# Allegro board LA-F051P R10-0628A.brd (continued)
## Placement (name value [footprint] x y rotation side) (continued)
PC1208  -  [C_0603]  130.4 65.17 270 top
PC1209  -  [C_0603]  129.13 65.17 270 top
PC1210  -  [C_0603]  99.52 58.77 270 bottom
PC1211  -  [C_0603]  99.77 66.09 270 top
PC1212  -  [C_0603]  97.04 61.85 90 bottom
PC1213  -  [C_0603]  92.46 42.86 270 bottom
PC1214  -  [C_0603]  98.35 61.85 90 top
PC1215  -  [C_0603]  97.04 61.85 90 top
PC1216  -  [C_0603]  95.86 71.71 90 top
PC1217  -  [C_0603]  110.39 64.61 90 top
PC1218  -  [C_0603]  99.64 61.83 90 bottom
PC1219  -  [C_0603]  126.14 58.81 90 top
PC1220  -  [C_0603]  123.67 58.12 90 top
PC1221  -  [C_0603]  126.09 65.24 270 top
PC1222  -  [C_0603]  124.82 65.24 270 top
PC1223  -  [C_0603]  123.55 65.24 270 top
PC1224  -  [C_0603]  109.12 64.55 90 top
PC1225  -  [C_0603]  126.09 61.17 90 top
PC1226  -  [C_0603]  111.66 64.61 90 top
PC1227  -  [C_0603]  115.29 64.6 90 top
PC1228  -  [C_0603]  123.55 61.17 90 top
PC1229  -  [C_0603]  112.88 64.6 90 top
PC1230  -  [C_0603]  98.3 71.71 90 top
PC1231  -  [C_0603]  94.15 42.87 270 bottom
PC1232  -  [C_0603]  101.07 69.49 270 bottom
PC1233  -  [C_0603]  97.08 71.71 90 top
PC1234  -  [C_0603]  102.27 69.49 270 bottom
PC1235  -  [C_0603]  100.98 66.09 270 top
PC1236  -  [C_0603]  98.57 66.09 270 top
PC1237  -  [C_0603]  129.9 75.78 180 bottom
PC1238  -  [C_0603]  98.4 71.73 90 bottom
PC1239  -  [C_0603]  97.13 71.73 90 bottom
PC1240  -  [C_0603]  98.34 61.83 90 bottom
PC1241  -  [C_0603]  95.86 71.73 90 bottom
PC1242  -  [C_0603]  102.27 69.49 270 top
PC1243  -  [C_0603]  103.47 69.49 270 top
PC1244  -  [C_0603]  92.46 42.86 270 top
PC1245  -  [C_0603]  101.07 69.49 270 top
PC1246  -  [C_0603]  103.47 69.49 270 bottom
PC1250  -  [C_0603]  102.18 66.09 270 top
PC1251  -  [C_0603]  103.39 66.09 270 top
PC1252  -  [C_0603]  104.59 66.09 270 top
PC1256  -  [C_0603]  101.07 61.81 90 top
PC1257  -  [C_0603]  99.68 61.86 90 top
PC1258  -  [C_0603]  107.54 61.81 90 top
PC1259  -  [C_0201]  134.58 66.02 0 top
PC1260  -  [C_0201]  127.74 63.46 180 top
PC1261  -  [C_0201]  127.74 60.92 180 top
PC1262  -  [C_0201]  134.47 60.28 0 top
PC1263  -  [C_0201]  134.47 65.36 0 top
PC1264  -  [C_0201]  134.47 61.55 0 top
PC1265  -  [C_0201]  134.47 62.82 0 top
PC1266  -  [C_0201]  127.74 59.65 180 top
PC1267  -  [C_0201]  127.74 62.82 180 top
PC1268  -  [C_0201]  127.74 64.73 180 top
PC1269  -  [C_0201]  127.15 66.73 90 top
PC1270  -  [C_0201]  99.59 68.06 0 top
PC1271  -  [C_0201]  99.59 67.5 0 top
PC1272  -  [C_0201]  126.57 66.76 90 top
PC1273  -  [C_0201]  99.58 68.63 0 top
PC1274  -  [C_0201]  125.4 66.76 90 top
PC1275  -  [C_0201]  128.75 67.78 0 top
PC1276  -  [C_0201]  116.28 67.75 180 top
PC1277  -  [C_0201]  116.19 65.45 90 top
PC1278  -  [C_0201]  120.37 56.85 270 top
PC1279  -  [C_0201]  120.98 56.78 0 top
PC1280  -  [C_0201]  123.8 56.85 270 top
PC1281  -  [C_0201]  126.21 56.85 270 top
PC1282  -  [C_0201]  119.1 56.85 270 top
PC1283  -  [C_0201]  125.07 56.85 270 top
PC1284  -  [C_0201]  116.59 67.18 180 top
PC1285  -  [C_0201]  127.36 56.77 270 top
PC1286  -  [C_0201]  118.85 64.42 270 top
PC1287  -  [C_0201]  118.25 64.42 270 top
PC1288  -  [C_0201]  127.74 61.55 180 top
PC1289  -  [C_0201]  125.98 66.79 90 top
PC1290  -  [C_0201]  99.59 66.93 0 top
PC1291  -  [C_0201]  132.28 56.73 0 top
PC1292  -  [C_0201]  131.69 56.17 180 top
PC1293  -  [C_0201]  127.74 59.01 180 top
PC1294  -  [C_0201]  134.47 60.92 0 top
PC1295  -  [C_0201]  134.47 62.19 0 top
PC1296  -  [C_0201]  134.47 64.73 0 top
PC1297  -  [C_0201]  127.74 60.28 180 top
PC1298  -  [C_0201]  127.74 62.19 180 top
PC1299  -  [C_0201]  127.74 64.09 180 top
PC1300  -  [C_0201]  127.46 67.98 180 top
PC1301  -  [C_0201]  133.71 55.58 90 top
PC1302  -  [C_0201]  134.47 63.46 0 top
PC1303  -  [C_0201]  131.67 56.73 180 top
PC1304  -  [C_0201]  134.47 64.09 0 top
PC1305  -  [C_0201]  132.27 56.17 0 top
PC1306  -  [C_B2]  97.21 45.98 90 bottom
PC1307  -  [C_B2]  98.03 51.19 0 bottom
PC1308  -  [C_B2]  97.18 59 90 bottom
PC1309  -  [C_B2]  97.16 65.6 180 bottom
PC1310  -  [C_0603]  133.15 73.34 90 top
PC1311  -  [C_0603]  137.71 72.83 270 top
PC1312  -  [C_0603]  76.68 67.01 180 bottom
PC1313  -  [C_0603]  134.38 73.36 90 top
PC1314  -  [C_0603]  135.67 73.36 90 top
PC1315  -  [C_0603]  136.97 68.79 90 top
PC1316  -  [C_0603]  138.79 64.86 0 top
PC1317  -  [C_0603]  138.02 59.9 0 top
PC1318  -  [C_0603]  137.64 63.71 180 top
PC1319  -  [C_0603]  137.64 66.25 180 top
PC1320  -  [C_0603]  137.64 64.98 180 top
PC1321  -  [C_0603]  76.68 68.28 180 bottom
PC1322  -  [C_0201]  138.28 58.63 180 top
PC1323  -  [C_0201]  138.88 58.63 0 top
PC1324  -  [C_0201]  138.66 67.9 0 top
PC1325  -  [C_0201]  137.64 67.9 180 top
PC1326  -  [C_0201]  136.41 67.78 180 top
PC1327  -  [C_0201]  135.69 68.73 90 top
PC1328  -  [C_0201]  134.85 66.63 0 top
PC1329  -  [C_B2]  96.79 68.79 180 bottom
PC1330  -  [C_0603]  124.82 61.17 90 top
PC1331  -  [C_0603]  102.46 61.81 90 top
PC1332  -  [C_0603]  103.73 61.81 90 top
PC1333  -  [C_0603]  119.86 58.12 90 top
PC1334  -  [C_0603]  108.81 61.81 90 top
PC1336  -  [C_0603]  124.89 58.81 90 top
PC1337  -  [C_0603]  122.4 58.12 90 top
PC1338  -  [C_0201]  119.25 67.52 90 top
PC1339  -  [C_0201]  121.12 67.51 90 top
PC1340  -  [C_0201]  120.19 67.5 90 top
PC1341  -  [C_0201]  118.42 67.88 180 top
PC1342  -  [C_0201]  117.2 66.72 90 top
PC1343  -  [C_0201]  116.76 65.46 90 top
PC1344  -  [C_0603]  121.13 58.12 90 top
PC1345  -  [C_0603]  111.35 61.81 90 top
PC1346  -  [C_0603]  110.08 61.81 90 top
PC1347  -  [C_0603]  122.28 65.11 270 top
PC1348  -  [C_0603]  121.01 65.11 270 top
PC1349  -  [C_0603]  119.74 65.11 270 top
PC1350  -  [C_0603]  111.6 60.36 270 top
PC1351  -  [C_0603]  115.04 60.54 270 top
PC1352  -  [C_0603]  113.26 60.41 270 top
PC1353  -  [C_0603]  115.29 61.81 90 top
PC1354  -  [C_0603]  113.26 61.81 90 top
PC1400  -  [C_0402]  174.73 53.48 90 top
PC1401  -  [C_0603]  177.78 51.52 0 bottom
PC1402  -  [C_0603]  177.78 50.91 0 top
PC1403  -  [C_0603]  169.58 52.16 0 top
PC1404  -  [C_0603]  167.87 50.89 180 top
PC1405  -  [C_0603]  168.63 52.16 180 top
PC1406  -  [C_0603]  193.97 72.09 180 top
PC1408  -  [C_0402]  177.65 49.64 0 top
PC1409  -  [C_0402]  177.65 50.38 0 bottom
PC1410  -  [C_0402]  168 48.22 90 top
PC1411  -  [C_0402]  174.85 46.69 270 top
PC1412  -  [C_0402]  202.68 74.47 180 bottom
PC1413  -  [C_0603]  202.96 76.73 0 top
PC1414  -  [C_0603]  202.32 78.14 0 top
PC1415  -  [C_0603]  193.97 73.36 180 top
PC1416  -  [C_0603]  193.97 74.63 180 top
PC1417  -  [C_0402]  202.97 74.81 0 top
PC1418  -  [C_0402]  202.96 75.69 0 top
PC1419  -  [C_0402]  196.44 70.82 180 top
PC1420  -  [C_0402]  202.45 72.68 90 bottom
PC1535  -  [C_0402]  63.14 63.47 0 bottom
PC1536  -  [C_0402]  59.13 32.88 270 top
PC1537  -  [C_D]  81.34 32.22 0 bottom
PC1538  -  [C_0402]  64.75 48.52 0 bottom
PD100  -  [TVNST52302AB0_SOT523-3]  67.29 14.82 180 top
PD101  -  [TVNST52302AB0_SOT523-3]  68.81 15.25 90 top
PD102  -  [AZ5125-01HPR7G_SOD523-2]  26.96 72.27 90 top
PD200  -  [BAT54CW_SOT323-3]  59.67 56.46 90 top
PD201  -  [SDMK0340L-7-F_SOD323-2]  90.33 77.05 180 top
PD202  -  [SDMK0340L-7-F_SOD323-2]  52.35 50.64 0 top
PD203  -  [SDMK0340L-7-F_SOD323-2]  89.69 70.32 180 top
PD204  -  [SDMK0340L-7-F_SOD323-2]  59.12 68.16 180 top
PD205  -  [SDMK0340L-7-F_SOD323-2]  59.14 69.88 180 top
PD206  -  [SDMK0340L-7-F_SOD323-2]  96.97 74.7 0 top
PD300  -  [SDMK0340L-7-F_SOD323-2]  42.14 22.56 270 top
PD301  -  [SDMK0340L-7-F_SOD323-2]  37.69 19.77 270 top
PD302  -  [SDMK0340L-7-F_SOD323-2]  39.47 19.77 270 top
PH1005  -  [R_0402]  85.17 58.99 0 bottom
PH1006  -  [R_0402]  71.5 59.18 0 bottom
PH1007  -  [R_0402]  84.25 59.91 0 bottom
PH1008  -  [R_0402]  84.32 50.69 0 bottom
PH1009  -  [R_0402]  89.18 42.91 0 bottom
PJP14  -  [JUMP_43X39]  28.68 19.77 270 bottom
PJP15  -  [JUMP_43X39]  170.36 63.13 180 top
PJP300  -  [JUMP_43X39]  41.76 30.74 90 top
PJP500  -  [JUMP_43X118]  76.18 17.91 270 bottom
PJP501  -  [JUMP_43X118]  59.03 46.78 90 bottom
PJP600  -  [JUMP_43X118]  162.83 21.04 180 top
PJP601  -  [JUMP_43X39]  164.64 27.77 180 top
PJP700  -  [JUMP_43X79]  192.55 56.09 180 bottom
PJP800  -  [JUMP_43X39]  168.12 71.54 270 top
PJP900  -  [JUMP_43X39]  161.85 42 180 top
PJP1002  -  [JUMP_43X118]  73.68 41.87 180 bottom
PJP1400  -  [JUMP_43X79]  169.27 53.89 90 top
PJP1401  -  [JUMP_43X79]  193.4 69.55 180 top
PL100  -  [TAI-T_HCB2012KF-121T50_2P]  76.09 24.29 180 bottom
PL101  -  [TAI-T_HCB2012KF-121T50_2P]  76.09 26.09 180 bottom
PL102  -  [MURAT_BLM15AG102SN1D_2P]  26.22 71.03 0 top
PL103  -  [TAI-T_HCB2012KF-121T50_2P]  28.55 78.19 0 bottom
PL104  -  [TAI-T_HCB2012KF-121T50_2P]  25.38 73.11 90 top
PL300  -  [TAI-T_HCB2012KF-121T50_2P]  49.2 31.57 90 bottom
PL301  -  [L_7X7X3_M_2P]  59.58 32.6 0 bottom
PL500  -  [TAI-T_HCB2012KF-121T50_2P]  92.86 25.95 270 bottom
PL501  -  [TAI-T_TMPC0518HP-1R5MG-D_2P]  85.57 20.66 180 bottom
PL504  -  [CYNTE_PCMC063T-1R5MN_2P]  59.28 42 180 bottom
PL600  -  [TAI-T_HCB2012KF-121T50_2P]  172.23 36.46 180 top
PL601  -  [CYNTE_PCMB051B-1R0MS_2P]  169.52 26.63 270 top
PL700  -  [TAI-T_HCB2012KF-121T50_2P]  196.71 66.91 270 bottom
PL701  -  [L_5X5X3_M_2P]  198.53 59.54 270 bottom
PL800  -  [TAI-T_HCB1608KF-121T3_L0603_2P]  177.65 79.21 180 top
PL801  -  [TOKO_1239AS-H-2R2N-P2_2P]  170.03 75.52 180 top
PL900  -  [TAI-T_HCB1608KF-121T3_L0603_2P]  173.27 38.78 90 top
PL901  -  [TOKO_1239AS-H-2R2N-P2_2P]  165.33 44.03 180 top
PL1004  -  [TAI-T_HCB2012KF-121T50_2P]  64.75 61.78 180 bottom
PL1005  -  [MAG_MMD05CZR47M_4P]  72.49 62.4 0 bottom
PL1100  -  [L_7X7X3_M]  87.58 47.11 0 bottom
PL1101  -  [L_7X7X3_M]  87.63 55.25 0 bottom
PL1102  -  [L_7X7X3_M]  87.66 62.9 0 bottom
PL1400  -  [TAI-T_HCB1608KF-121T3_L0603_2P]  179.55 52.18 180 top
PL1401  -  [TOKO_1277AS-H-1R0N-P2_2P]  169.9 48.47 90 top
PL1402  -  [TAI-T_HCB1608KF-121T3_L0603_2P]  199.44 77.83 0 top
PL1403  -  [TOKO_1277AS-H-1R0N-P2_2P]  196.06 73.24 90 top
PQ100  -  [FDV301N_NL_SOT23-3]  27.65 69.25 180 top
PQ101  -  [MMST3904-7-F_SOT323-3]  31.68 72.06 0 top
PQ200  -  [AON2405_DFN6-8]  56 51.55 180 bottom
PQ201  -  [AON2405_DFN6-8]  56.21 56.36 270 bottom
PQ202  -  [AON2405_DFN6-8]  33.14 75.17 180 bottom
PQ203  -  [AON2405_DFN6-8]  34.42 75.25 90 bottom
PQ204  -  [NTR4502PT1G_SOT23-3]  57.86 50.86 0 top
PQ205  -  [NTR4502PT1G_SOT23-3]  18.77 76.82 180 top
PQ206  -  [DMN66D0LDW-7_SOT363-6]  58.4 55.7 90 top
PQ207  -  [DMN66D0LDW-7_SOT363-6]  34.87 75.61 180 top
PQ208  -  [DMN66D0LDW-7_SOT363-6]  62.96 47.57 90 top
PQ209  -  [DMN66D0LDW-7_SOT363-6]  21.07 72.92 180 top
PQ210  -  [AON2405_DFN6-8]  46.61 74.49 90 bottom
PQ211  -  [AON2405_DFN6-8]  46.82 78.67 0 bottom
PQ212  -  [AON2405_DFN6-8]  45.57 76.92 180 bottom
PQ213  -  [NTR4502PT1G_SOT23-3]  57.96 61.77 180 top
PQ214  -  [NTR4502PT1G_SOT23-3]  47.85 73.16 90 top
PQ215  -  [DMN66D0LDW-7_SOT363-6]  60.08 65.48 180 top
PQ216  -  [DMN66D0LDW-7_SOT363-6]  57.7 65.48 180 top
PQ217  -  [DMN66D0LDW-7_SOT363-6]  55.08 73.1 90 top
PQ218  -  [DMN66D0LDW-7_SOT363-6]  88.43 68.55 270 top
PQ219  -  [DMN66D0LDW-7_SOT363-6]  62.44 19.84 0 top
PQ220  -  [SSM3K7002FU_SC70-3]  58.72 20.53 270 top
PQ221  -  [NTR4502PT1G_SOT23-3]  56.24 40.47 180 top
PQ222  -  [NTR4502PT1G_SOT23-3]  64.48 33.96 90 top
PQ223  -  [DMN66D0LDW-7_SOT363-6]  58.18 32.86 90 top
PQ224  -  [SSM3K7002FU_SC70-3]  56.06 67.5 0 bottom
PQ302  -  [L2N7002WT1G_SC70-3]  39.02 22.58 90 top
PQ303  -  [SIR472DP-T1-GE3_POWERPAK8-5]  56.64 29.54 270 bottom
PQ304  -  [SI7716ADN-T1-GE3_POWERPAK8-5]  54.09 31.62 90 bottom
PQ305  -  [SI4483ADY-T1-GE3_SO8]  74.24 33.33 0 bottom
PQ400  -  [DMN66D0LDW-7_SOT363-6]  166.79 58.27 270 top
PQ1302  -  [AON7934_DFN3X3A8-10]  69.85 62.15 180 bottom
PR100  -  [R_0402]  66.02 18.88 270 top
PR101  -  [R_0402]  27.97 71.05 0 top
PR102  -  [R_0402]  23.44 69.8 270 top
PR103  -  [R_0402]  25.24 68.75 180 top
PR104  -  [R_0402]  28.93 72.02 90 top
PR105  -  [R_0402]  33.39 72.62 0 top
PR106  -  [R_0402]  29.82 72.93 270 top
PR107  -  [R_0805]  29.21 76.51 270 top
PR108  -  [R0402_0OHM]  28 72.01 90 top
PR200  -  [R_1206_4P-D]  55.07 58.87 90 bottom
PR201  -  [R_0402]  60.27 51.61 90 top
PR202  -  [R_0402]  55.14 54.06 0 bottom
PR203  -  [R_0402]  29.44 76.74 270 bottom
PR204  -  [R_0402]  18.59 72.98 180 top
PR205  -  [R_0402]  35.74 78.95 180 bottom
PR206  -  [R_0402]  21.23 76.29 0 top
PR207  -  [R_0402]  59.35 54.73 0 top
PR208  -  [R_0402]  34.49 76.55 180 top
PR209  -  [R_0402]  31.48 75.1 0 top
PR210  -  [R_0402]  60.94 45.69 90 top
PR211  -  [R_0402]  17.68 72.09 0 top
PR212  -  [R_0402]  20.22 70.06 0 top
PR213  -  [R_0402]  61.68 58.51 0 top
PR214  -  [R_0402]  61.02 62.59 270 bottom
PR215  -  [R_0402]  22.15 77.3 180 top
PR216  -  [R_0402]  60.52 59.13 270 top
PR217  -  [R_0402]  21.18 74.96 270 top
PR218  -  [R_0402]  62.09 49.93 180 top
PR219  -  [R_0402]  32.6 76.12 180 top
PR220  -  [R_0402]  22.07 74.96 270 top
PR221  -  [R_0402]  57.51 61.63 270 bottom
PR222  -  [R_0402]  56.62 59.78 90 bottom
PR223  -  [R_0402]  56.6 57.87 0 bottom
PR224  -  [R_0402]  92.25 73.62 180 top
PR225  -  [R_0402]  57.51 58.76 90 bottom
PR226  -  [R_0402]  87.4 75.52 0 top
PR227  -  [R_0402]  91.34 75.52 0 top
PR228  -  [R_0402]  36 74.35 270 top
PR229  -  [R_0402]  59.96 46.62 270 top
PR230  -  [R_0402]  91.34 72.73 0 top
PR232  -  [R_0402]  50.67 75.14 270 bottom
PR233  -  [R_0402]  59.49 66.26 90 bottom
PR234  -  [R_0402]  50.39 77.73 90 bottom
PR235  -  [R_0402]  49.53 71.79 0 top
PR237  -  [R_0402]  44.17 78.05 270 top
PR239  -  [R_0402]  51.36 79.59 180 bottom
PR240  -  [R_0402]  63.14 64.35 0 bottom
PR241  -  [R_0402]  51.56 75.28 90 bottom
PR242  -  [R_0402]  58.6 67.19 180 bottom
PR243  -  [R_0402]  50.44 80.48 0 bottom
PR244  -  [R_0402]  42.52 77.36 90 top
PR245  -  [R_0402]  49.56 72.67 0 top
PR246  -  [R_0402]  61.44 65.06 270 bottom
PR247  -  [R_0402]  54.42 64.3 90 bottom
PR248  -  [R_0402]  53.24 66.15 90 top
PR249  -  [R_0402]  52.9 68.64 180 top
PR250  -  [R_0402]  53.68 71.66 0 top
PR251  -  [R_0402]  51.35 72.22 0 top
PR252  -  [R_0402]  85.7 68.74 270 top
PR253  -  [R_0402]  92.25 68.8 180 top
PR254  -  [R_0402]  84 70.82 180 top
PR255  -  [R_0402]  63.22 23.66 270 top
PR256  -  [R_0402]  64.87 20.86 270 top
PR257  -  [R_0402]  62.33 23.66 270 top
PR258  -  [R_0402]  85.83 69.86 90 top
PR259  -  [R_0402]  64.95 16.47 180 top
PR260  -  [R_0402]  56.03 18.63 0 top
PR261  -  [R_0402]  56.03 20.41 0 top
PR262  -  [R_0402]  64.03 15.58 0 top
PR263  -  [R_0402]  58.4 15.27 270 top
PR264  -  [R_0402]  82.65 74.08 270 top
PR265  -  [R_0402]  86.59 68.74 270 top
PR266  -  [R_0402]  64.95 13.8 180 top
PR267  -  [R_0402]  59.28 14.36 90 top
PR268  -  [R_0402]  83.54 73.16 90 top
PR269  -  [R_0402]  84.38 72.22 180 top
PR270  -  [R_0402]  64.03 14.69 0 top
PR271  -  [R_0402]  64.03 17.36 0 top
PR272  -  [R_0402]  57.51 15.27 270 top
PR273  -  [R_0402]  56.95 17.48 180 top
PR274  -  [R_0402]  91.34 67.9 0 top
PR275  -  [R_0402]  56.02 36.67 0 top
PR277  -  [R_0402]  60.03 31.97 90 top
PR278  -  [R_0402]  60.55 34.63 270 top
PR279  -  [R_0402]  59.67 34.65 270 top
PR280  -  [R_0402]  57.38 54.66 0 top
PR281  -  [R_0402]  55.11 35.78 0 top
PR282  -  [R_0402]  60.11 47.57 90 top
PR283  -  [R_0402]  62.36 47.08 270 bottom
PR284  -  [R_0402]  60.36 62.56 180 top
PR285  -  [R_0402]  54.42 67 270 bottom
PR286  -  [R_0402]  58.06 66.8 180 top
PR287  -  [R_0402]  93.18 70.6 180 top
PR288  -  [R_0402]  91.39 69.69 90 top
PR289  -  [R_0402]  64.36 59 180 top
PR290  -  [R_0402]  59.27 57.98 180 top
PR291  -  [R_0402]  55.18 67.85 180 bottom
PR300  -  [R_1206_4P-D]  49.25 29.46 270 bottom
PR301  -  [R_0402]  35.92 23.02 270 top
PR303  -  [R0402_0OHM]  45.39 23.96 180 bottom
PR304  -  [R0402_0OHM]  45.39 24.85 180 bottom
PR305  -  [R_0402]  42.29 24.27 90 bottom
PR306  -  [R_1206]  44.04 22.95 90 top
PR307  -  [R_0402]  39.47 22.11 90 bottom
PR308  -  [R_0603]  45.95 29.8 0 bottom
PR309  -  [R0402_0OHM]  37.64 30.31 180 bottom
PR310  -  [R_0402]  38.58 22.11 90 bottom
PR311  -  [R0402_0OHM]  37.64 31.71 180 bottom
PR312  -  [R_0402]  41.25 24.27 90 bottom
PR313  -  [R_1206_4P-D]  72.15 33.23 180 bottom
PR314  -  [R0402_0OHM]  42.14 22.11 90 bottom
PR315  -  [R0402_0OHM]  38.46 24.27 90 bottom
PR316  -  [R_0402]  36.73 29.17 0 bottom
PR317  -  [R_0402]  41.25 23.02 270 bottom
PR318  -  [R0402_0OHM]  40.36 24.27 90 top
PR319  -  [R0402_0OHM]  40.48 26.82 180 top
PR320  -  [R_0402]  45.24 32.34 0 bottom
PR321  -  [R_1206]  56.9 35.52 180 bottom
PR322  -  [R_0402]  39.25 27.71 0 top
PR323  -  [R_0402]  41.61 33.64 90 bottom
PR324  -  [R_0603]  39.22 33.11 90 bottom
PR325  -  [R_0402]  37.69 32.98 0 top
PR326  -  [R0402_0OHM]  37.69 32.09 0 top
PR327  -  [R_0402]  38.58 33.87 180 top
PR400  -  [R_0402]  164.69 63.38 90 bottom
PR401  -  [R_0402]  167.44 57.24 180 bottom
PR402  -  [R_0402]  167.95 64.47 180 top
PR403  -  [R_0402]  169.01 60.23 270 top
PR404  -  [R_0402]  169.9 60.23 270 top
PR405  -  [R_0402]  166.52 58.12 0 bottom
PR406  -  [R_0402]  167.03 63.59 0 top
PR407  -  [R_0402]  174.14 55.71 0 top
PR408  -  [R_0402]  167.95 62.7 180 top
PR409  -  [R_0402]  167.95 61.81 180 top
PR410  -  [R_0402]  166.6 59.06 90 bottom
PR411  -  [R_0402]  163.81 60.79 270 bottom
PR412  -  [R_0402]  167.03 60.92 0 top
PR413  -  [R_0402]  165.71 59.98 270 bottom
PR500  -  [R_0603]  88.81 22.31 180 top
PR501  -  [R_1206]  84.68 21.1 90 top
PR502  -  [R_0402]  88.37 17.94 270 bottom
PR503  -  [R0402_0OHM]  91.03 17.03 90 bottom
PR504  -  [R_0402]  89.26 17.03 90 bottom
PR505  -  [R_0603]  62.41 43.79 180 top
PR506  -  [R_0402]  67.16 38.36 90 bottom
PR507  -  [R_1206]  59.25 42.25 270 top
PR508  -  [R_0402]  66.27 38.36 90 bottom
PR509  -  [R_0402]  65.38 39.28 270 bottom
PR510  -  [R0402_0OHM]  64.49 38.36 90 bottom
PR511  -  [R_0402]  62.71 38.36 90 bottom
PR512  -  [R0805_0OHM]  70.28 42.67 90 top
PR513  -  [R0805_0OHM]  70.28 42.67 90 bottom
PR600  -  [R_0402]  175.29 35.26 0 top
PR601  -  [R_0402]  175.29 34.38 0 top
PR602  -  [R_0603]  172.96 25.59 270 top
PR603  -  [R_0402]  173.41 31.58 180 top
PR604  -  [R_0402]  173.41 34.25 180 top
PR605  -  [R_0402]  172.49 32.47 0 top
PR606  -  [R0402_0OHM]  172.49 33.36 0 top
PR607  -  [R0402_0OHM]  166.73 33.87 270 top
PR608  -  [R_0402]  165.84 32.98 90 top
PR609  -  [R0402_0OHM]  163.04 31.2 0 top
PR610  -  [R_0402]  163.93 30.31 180 top
PR611  -  [R_0402]  163.04 32.09 0 top
PR612  -  [R_0603]  172.54 27.87 0 top
PR700  -  [R_0402]  204.05 67.17 180 bottom
PR701  -  [R_0402]  203.15 66.29 0 bottom
PR702  -  [R_0603]  202.03 60.92 270 bottom
PR703  -  [R_0603]  198.98 62.63 270 top
PR704  -  [R_0402]  203.98 62.73 180 bottom
PR705  -  [R_0402]  200.67 66.71 90 bottom
PR707  -  [R_0402]  203.14 64.51 0 bottom
PR708  -  [R_0402]  203.14 63.13 90 top
PR709  -  [R0402_0OHM]  204.03 64.04 270 top
PR800  -  [R_0402]  173.08 78.95 270 top
PR801  -  [R0402_0OHM]  172.2 78.95 270 top
PR802  -  [R_0402]  171.55 70.82 90 top
PR803  -  [R_0603]  170.03 77.43 90 top
PR804  -  [R_0402]  172.44 71.71 270 top
PR805  -  [R_0402]  169.77 70.8 90 top
PR806  -  [R0402_0OHM]  173.33 70.8 90 top
PR900  -  [R0402_0OHM]  173.2 43.4 180 top
PR901  -  [R_0402]  173.2 44.28 180 top
PR902  -  [R_0402]  167.62 38.19 90 top
PR903  -  [R_0805]  165.29 41.87 180 top
PR904  -  [R_0402]  165.79 38.95 180 top
PR905  -  [R_0402]  165.41 40.47 180 top
PR906  -  [R0402_0OHM]  169.01 38.11 90 top
PR1024  -  [R0402_0OHM]  61.44 53.81 0 top
PR1025  -  [R0402_0OHM]  61.44 54.7 0 top
PR1027  -  [R0402_0OHM]  63.6 51.01 0 top
PR1028  -  [R_0402]  63.6 54.7 0 top
PR1029  -  [R0402_0OHM]  63.6 50.12 0 top
PR1058  -  [R_0402]  65.76 58.17 90 bottom
PR1059  -  [R0402_0OHM]  63.3 65.24 180 top
PR1060  -  [R_0402]  71.48 58.25 90 top
PR1061  -  [R_0402]  71.48 48.22 90 bottom
PR1062  -  [R_0402]  70.59 46.82 0 bottom
PR1063  -  [R_0402]  64.49 53.81 180 bottom
PR1064  -  [R_0402]  74.78 52.28 180 top
PR1065  -  [R_0402]  67.79 46.06 90 top
PR1066  -  [R0402_0OHM]  63.48 55.58 90 bottom
PR1067  -  [R_0402]  65 46.06 90 top
PR1068  -  [R_0402]  74.91 57.62 0 top
PR1069  -  [R_0402]  70.49 56.63 270 bottom
PR1070  -  [R_0402]  63.6 52.92 0 top
PR1071  -  [R_0402]  71.1 51.39 0 bottom
PR1072  -  [R_0402]  65.13 48.09 90 top
PR1073  -  [R_0402]  70.59 58.25 90 top
PR1074  -  [R_0402]  64.49 54.7 180 bottom
PR1075  -  [R_0402]  66.65 58.17 90 top
PR1076  -  [R0402_0OHM]  63.6 53.81 0 top
PR1077  -  [R_0402]  69.57 58.25 180 top
PR1078  -  [R_0402]  73.64 55.13 0 bottom
PR1079  -  [R_0402]  73.89 54.06 270 top
PR1080  -  [R0402_0OHM]  65.8 55.23 90 bottom
PR1081  -  [R_0402]  75.79 53.17 180 top
PR1082  -  [R_0603]  61.57 62.82 90 top
PR1083  -  [R0402_0OHM]  64.24 48.09 90 top
PR1084  -  [R_0402]  64.49 52.92 180 bottom
PR1085  -  [R_0402]  74.91 56.73 0 top
PR1086  -  [R_1206]  73.25 67.4 180 bottom
PR1087  -  [R_0402]  72.37 48.22 90 bottom
PR1088  -  [R_0402]  69.57 46.95 270 bottom
PR1089  -  [R_0402]  64.87 58.17 90 bottom
PR1090  -  [R_0402]  67.56 56.66 180 bottom
PR1091  -  [R_0603]  65.7 60.16 180 bottom
PR1092  -  [R_0402]  67.54 60.03 180 top
PR1093  -  [R_0402]  68.68 48.22 180 top
PR1094  -  [R_0402]  64.49 55.58 180 top
PR1095  -  [R_0402]  63.6 51.9 0 top
PR1096  -  [R_0402]  76.18 52.28 0 top
PR1097  -  [R_0402]  73.76 54.24 0 bottom
PR1098  -  [R_0402]  68.81 45.93 90 top
PR1099  -  [R_0402]  66.69 51.52 270 bottom
PR1100  -  [R_0603]  77.33 49.98 0 bottom
PR1101  -  [R_1206]  87.9 47.67 180 top
PR1102  -  [R_0603]  75.03 57.97 180 bottom
PR1103  -  [R0402_0OHM]  78.75 47.1 180 bottom
PR1105  -  [R_0603]  78.16 56.71 90 bottom
PR1106  -  [R_1206]  87.78 55.29 180 top
PR1107  -  [R_0402]  76.24 48.1 270 bottom
PR1109  -  [R_0402]  74.59 49.03 90 bottom
PR1110  -  [R0402_0OHM]  78.36 54.81 180 bottom
PR1111  -  [R_0603]  75.67 50.5 270 bottom
PR1112  -  [R_0402]  73.7 49.03 90 bottom
PR1113  -  [R_0603]  79.57 67.6 270 bottom
PR1114  -  [R_1206]  87.77 63.65 180 top
PR1115  -  [R_0402]  74.52 46.9 270 bottom
PR1116  -  [R_0603]  73.44 47.96 0 bottom
PR1118  -  [R_0402]  73.64 46.9 270 bottom
PR1119  -  [R0402_0OHM]  77.38 57.68 270 top
PR1120  -  [R_0402]  73.62 45.11 0 bottom
PR1121  -  [R_0402]  64.49 56.6 180 top
PR1122  -  [R_0402]  66.02 48.09 90 top
PR1123  -  [R_0402]  71.13 54.05 0 bottom
PR1124  -  [R_0402]  61.44 51.9 0 top
PR1125  -  [R0402_0OHM]  61.44 52.92 0 top
PR1126  -  [R_0402]  73.81 51.39 0 top
PR1127  -  [R_0402]  69.7 49.11 270 top
PR1128  -  [R_0402]  73.76 50.5 0 top
PR1400  -  [R0402_0OHM]  172.95 54.39 270 top
PR1401  -  [R0402_0OHM]  176.51 54.26 270 top
PR1402  -  [R_0402]  175.62 53.35 90 top
PR1403  -  [R_0603]  170.35 47.2 180 top
PR1404  -  [R_0402]  176.63 45.81 90 top
PR1405  -  [R_0402]  178.21 47.76 90 top
PR1406  -  [R_0402]  175.74 46.69 270 top
PR1407  -  [R_0402]  177.32 48.68 270 top
PR1408  -  [R_0402]  171.3 45.81 90 top
PR1409  -  [R0402_0OHM]  172.19 46.69 270 top
PR1411  -  [R0402_0OHM]  196.34 79.87 270 top
PR1412  -  [R_0402]  203.59 73.43 90 bottom
PR1413  -  [R_0402]  202.68 75.36 180 bottom
PR1414  -  [R_0402]  204.06 69.43 90 top
PR1415  -  [R_0402]  203.89 72.98 180 top
PR1416  -  [R_0603]  195.17 71.97 0 top
PR1417  -  [R_0402]  202.92 71.21 0 top
PR1418  -  [R_0402]  202.97 73.87 0 top
PR1419  -  [R0402_0OHM]  203.89 72.09 180 top
PR1420  -  [R0402_0OHM]  203.18 69.43 90 top
PR1421  -  [R0402_0OHM]  200.67 72.68 90 bottom
PR1422  -  [R_0402]  201.56 72.68 90 bottom
PR1423  -  [R_0402]  173.84 54.39 270 top
PR1424  -  [R_0402]  197.23 79.87 270 top
PR1425  -  [R_0402]  63.88 48.24 90 bottom
PRP100  -  [RP_0804_8P4R]  67.16 17.87 90 top
PU200  -  [INA199A1DCKR_SC70-6]  59.81 59.01 180 bottom
PU201  -  [LM393DMR2G_MICRO8]  89.85 72.01 90 top
PU202  -  [RT9069-33GB_SOT23-5]  65.41 67.45 270 bottom
PU203  -  [LM393DMR2G_MICRO8]  58.18 18.46 270 top
PU300  -  [BQ24777ARUYR_WQFN28_4X4]  42.9 27.26 90 bottom
PU400  -  [LM393DMR2G_MICRO8]  163.85 59.94 0 top
PU401  -  [M74VHC1GT00DFT2G_SC70-5]  169.71 58.27 270 top
PU402  -  [M74VHC1GT00DFT2G_SC70-5]  172.51 58.27 270 top
PU500  -  [SY8286BRAC_QFN20_3X3]  88.88 22.31 270 bottom
PU501  -  [SY8288CRAC_QFN20_3X3]  62.59 44.03 270 bottom
PU600  -  [SY8210AQVC_QFN19_4X3]  168 32.67 0 top
PU700  -  [SY8286RAC_QFN20_3X3]  198.48 62.91 0 bottom
PU800  -  [TLV62150RGTR_QFN16_3X3]  171.68 75.78 270 top
PU900  -  [TLV62150RGTR_QFN16_3X3]  166.98 42.88 270 top
PU1000  -  [ISL95859AHRTZ-T_TQFN40_5X5]  67.16 51.01 90 top
PU1100  -  [AOZ5049QI_QFN24_5X3P5-S]  80 46.71 90 bottom
PU1101  -  [AOZ5049QI_QFN24_5X3P5-S]  80.06 54.63 90 bottom
PU1102  -  [AOZ5049QI_QFN24_5X3P5-S]  80.06 62.21 90 bottom
PU1305  -  [ISL95808HRZ-TS2378_DFN8_2X2]  62.97 61.68 0 top
PU1400  -  [TPS62134ARGT_QFN16_3X3]  172.92 50.62 0 top
PU1401  -  [TPS62134BRGT_QFN16_3X3]  198.48 75.35 0 top
Q40  -  [L2N7002WT1G_SC-70-3]  183.57 18.62 180 top
Q41  -  [L2N7002WT1G_SC-70-3]  7.28 5.95 90 top
Q70  -  [SI3457BDV-T1-E3_TSOP6]  198.41 18.99 270 top
Q71  -  [L2N7002WT1G_SC-70-3]  203.37 17.74 90 top
Q72  -  [DMG2301U-7_SOT23-3]  198.16 46.06 90 top
QA1  -  [DMN66D0LDW-7_SOT363-6]  16.72 25.68 0 top
QA3  -  [DMN66D0LDW-7_SOT363-6]  16.37 32.09 180 top
QA6  -  [SSM3K7002FU_SC70-3]  19.03 31.52 180 top
QA9  -  [SSM3K7002FU_SC70-3]  19.28 24.53 180 top
QC2  -  [DMN66D0LDW-7_SOT363-6]  158.22 63.33 0 top
QE3  -  [MMBT3904WT1G_SC70-3]  135.99 61.81 270 top
QE4  -  [MMBT3904WT1G_SC70-3]  109.58 45.55 270 bottom
QE8  -  [MMBT3904WT1G_SC70-3]  193.9 79.97 180 top
QE9  -  [MMST3904-7-F_SOT323-3]  175.11 68.99 0 top
QE10  -  [MMBT3904WT1G_SC70-3]  148.95 36.66 0 top
QE11  -  [MMBT3904WT1G_SC70-3]  26.33 56.92 270 bottom
QE12  -  [DMN66D0LDW-7_SOT363-6]  187.55 74.76 270 top
QE13  -  [DMN66D0LDW-7_SOT363-6]  158.58 37.24 0 top
QE14  -  [DMN66D0LDW-7_SOT363-6]  34.18 35.23 270 top
QH7  -  [DMN66D0LDW-7_SOT363-6]  189.71 15.07 0 top
QH8  -  [DMN66D0LDW-7_SOT363-6]  9.05 7.75 90 top
QH9  -  [DMN66D0LDW-7_SOT363-6]  9.05 10.17 90 top
QT19  -  [L2N7002WT1G_SC-70-3]  27.74 54.14 180 bottom
QZ9  -  [DMG2301U-7_SOT23-3]  57.12 73.09 270 top
R7  -  [R_0402]  27.18 37.17 90 top
R9  -  [R_0201]  141.07 57.43 270 top
R10  -  [R_0201]  158.66 60.55 270 top
R60  -  [R_0201]  186.42 49.12 90 top
R78  -  [R_0402]  159.04 40.99 270 top
R79  -  [R_0402]  160.71 36.09 180 top
R80  -  [R_0402]  32.79 34.83 270 top
R81  -  [R_0402]  37.06 35.12 90 top
R104  -  [R0402_0OHM]  42.63 53.3 90 bottom
R220  -  [R_0402]  185.65 40.6 270 bottom
R249  -  [R_0402]  188.98 63.41 270 bottom
R250  -  [R0402_0OHM]  188.09 63.23 180 bottom
R251  -  [R0402_0OHM]  191.44 62.95 180 top
R252  -  [R_0402]  173.2 67.52 0 top
R287  -  [R_0402]  188.49 28.79 0 bottom
R288  -  [R_0402]  188.49 27.9 0 bottom
R289  -  [R0402_0OHM]  203.1 31.96 270 top
R290  -  [R_0402]  54.66 19.26 180 top
R291  -  [R_0402]  198.78 27.9 0 top
R292  -  [R_0402]  198.78 26.5 0 top
R531  -  [R_0603]  196.06 17.8 90 top
R535  -  [R_0402]  199.67 14.31 0 top
R536  -  [R_0402]  201.52 15.27 270 top
R540  -  [R_0402]  193.02 27.52 180 top
R545  -  [R_0402]  193.02 29.42 180 top
R884  -  [R_0402]  162.79 15.2 0 top
R886  -  [R_0402]  163.68 17.23 180 top
R910  -  [R_0402]  6.2 5.93 180 top
R911  -  [R_0402]  6.2 9.48 180 top
R912  -  [R_0402]  6.2 8.59 180 top
R913  -  [R_0402]  6.2 7.71 180 top
R916  -  [R_0402]  6.2 6.82 180 top
R1006  -  [R_0402]  183.74 50.2 270 top
R1027  -  [R_0402]  204.14 42.38 180 top
R1103  -  [R_0402]  165.25 16.21 0 top
R1104  -  [R_0402]  189.71 18.25 0 top
R1105  -  [R_0402]  190.98 14.06 180 top
R1125  -  [R0603_0OHM]  30.71 40.79 270 top
R1140  -  [R_0402]  53.75 20.15 0 top
R1141  -  [R_0402]  53.75 21.04 0 top
R1161  -  [R_0402]  206.48 18.55 90 top
R1162  -  [R_0402]  61.06 76.46 90 top
R1175  -  [R_0402]  168.61 14.18 0 top
R1176  -  [R_0402]  172.31 14.97 270 top
R1178  -  [R_0402]  171.43 14.97 270 top
R1179  -  [R_0402]  62.12 75.76 90 top
R1186  -  [R_0402]  36.81 39 90 top
R1187  -  [R_0402]  181.08 36.04 270 top
R1188  -  [R_0402]  179.17 37.82 270 top
R1191  -  [R_0402]  158.73 51.14 180 top
R1200  -  [R0402_0OHM]  43.46 46.95 0 top
R1210  -  [R0402_0OHM]  43.36 47.81 0 top
R1212  -  [R0402_0OHM]  42.14 45.93 90 top
R1216  -  [R_0402]  23.67 52.79 180 top
R1255  -  [R_0402]  44.16 45.09 270 top
R1299  -  [R_0402]  184 22.18 180 top
R1318  -  [R0603_0OHM]  34.27 39.46 270 top
R1320  -  [R0603_0OHM]  48.55 21.73 180 top
R1322  -  [R0805_0OHM]  200.75 38.31 180 top
R1323  -  [R0603_0OHM]  168.89 18.5 270 top
R1325  -  [R0603_0OHM]  162.09 66.38 180 top
R1326  -  [R0805_0OHM]  177.61 29.42 180 top
R1327  -  [R0603_0OHM]  153.26 75.14 180 top
R1329  -  [R0805_0OHM]  39.6 43.81 90 top
R1333  -  [R0603_0OHM]  160.88 47.58 180 top
R1335  -  [R0603_0OHM]  155.51 78.14 180 top
R1342  -  [R0805_0OHM]  181.33 29.76 270 top
R1343  -  [R0603_0OHM]  173.77 19.01 0 top
R1344  -  [R0805_0OHM]  35.66 45.08 90 top
R1376  -  [R_0402]  175.36 31.76 90 top
R1377  -  [R_0402]  175.29 36.51 0 top
R1393  -  [R0805_0OHM]  179.81 44.66 0 top
R1403  -  [R_0201]  51.54 54.73 90 top
R1405  -  [R_0201]  43.07 54.02 0 top
R1436  -  [R0402_0OHM]  26.94 67.9 90 bottom
R1437  -  [R0402_0OHM]  27.55 58.66 0 top
R1438  -  [R0402_0OHM]  17.88 61 0 top
R1439  -  [R0402_0OHM]  28.14 60.56 0 top
R1440  -  [R0402_0OHM]  28.35 55.36 90 bottom
R1441  -  [R0402_0OHM]  17.81 66.05 0 top
R1442  -  [R0402_0OHM]  17.81 66.94 0 top
R1443  -  [R_0402]  182.86 36.04 270 top
R1444  -  [R0402_0OHM]  181.97 36.04 270 top
R1445  -  [R0402_0OHM]  180.06 36.04 270 top
R1446  -  [R_0402]  179.17 36.04 270 top
R1454  -  [R_0402]  28.98 63.44 180 top
R1457  -  [R_0201]  18.64 58.63 180 top
R1458  -  [R_0201]  18.3 59.22 180 top
R1459  -  [R_0201]  16.57 61.05 0 top
R1460  -  [R_0402]  29.19 62.57 180 top
R1461  -  [R_0201]  20.98 62.39 90 bottom
R1462  -  [R_0402]  27.89 51.14 270 bottom
R1463  -  [R_0201]  16.45 63.97 0 top
R1464  -  [R_0201]  17.03 63.33 180 top
R1465  -  [R_0201]  22.67 55.63 270 top
R1468  -  [R_0402]  23.65 57.74 270 top
R1471  -  [R_0201]  25.22 67.97 180 top
R1472  -  [R_0402]  21.18 67.28 270 top
R1473  -  [R_0402]  23.15 62.77 270 bottom
R1474  -  [R_0402]  23.47 38.11 90 top
R1475  -  [R_0402]  28.98 64.32 180 top
R1476  -  [R_0402]  22.2 47.75 0 top
R1477  -  [R_0402]  20.93 38.11 90 top
R1478  -  [R_0402]  17.81 65.16 0 top
R1873  -  [R_0402]  182.86 50.2 270 top
R2662  -  [R_0402]  174.35 41.09 90 top
R2663  -  [R0402_0OHM]  186.67 32.98 180 bottom
R2664  -  [R0402_0OHM]  186.67 33.87 180 bottom
R2665  -  [R0402_0OHM]  155.25 68.74 0 bottom
R2669  -  [R0805_0OHM]  48.36 18.25 180 top
R2670  -  [R0603_0OHM]  55.31 75.61 180 top
R2671  -  [R0603_0OHM]  55.73 78.25 90 top
R2672  -  [R_0805]  181.43 46.97 180 top
RA15  -  [R_0402]  15.8 27.59 180 bottom
RA16  -  [R_0402]  17.37 23.76 90 top
RA17  -  [R_0402]  19.71 24.72 0 bottom
RA18  -  [R_0402]  19.15 19.82 90 top
RA19  -  [R_0402]  19.66 33.94 270 bottom
RA20  -  [R_0402]  15.8 29.42 180 bottom
RA24  -  [R_0402]  25.4 38.08 270 top
RA25  -  [R_0402]  26.29 38.08 270 top
RA26  -  [R0402_0OHM]  14.88 30.31 0 bottom
RA27  -  [R_0402]  8.74 23.15 270 bottom
RA28  -  [R_0402]  8.31 23.33 180 top
RA30  -  [R0402_0OHM]  19.66 32.17 270 bottom
RA31  -  [R0402_0OHM]  17.37 28.77 90 top
RA35  -  [R_0402]  14.83 31.38 90 bottom
RA37  -  [R_0402]  14.9 34.83 270 top
RA38  -  [R_0402]  16.68 30.32 270 bottom
RA39  -  [R_0402]  14.88 33.04 0 top
RA41  -  [R_0402]  18.26 20.74 270 top
RA48  -  [R_0402]  20.55 26.58 270 bottom
RA49  -  [R_0402]  17.56 28.55 270 bottom
RA50  -  [R_0402]  19.66 26.58 270 top
RA51  -  [R_0402]  18.45 28.55 270 bottom
RA54  -  [R0402_0OHM]  25.55 34.38 0 top
RA57  -  [R_0402]  20.04 19.82 90 top
RA58  -  [R_0402]  33.96 28.28 180 top
RA59  -  [R0402_0OHM]  31.22 24.09 90 top
RA60  -  [R_0402]  16.68 27.63 90 bottom
RA61  -  [R_0402]  19.66 25.66 90 bottom
RA62  -  [R_0402]  33.96 31.2 180 top
RA63  -  [R0402_0OHM]  24.36 26.96 270 bottom
RA64  -  [R0402_0OHM]  7.98 22.39 270 top
RA65  -  [R0402_0OHM]  7.85 22.23 90 bottom
RA75  -  [R_0402]  29.31 34.3 90 top
RA76  -  [R_0402]  31.17 34.38 180 top
RA77  -  [R_0402]  22.15 32.09 180 top
RA80  -  [R0603_0OHM]  32.8 36.15 0 bottom
RA81  -  [R_0603]  34.65 22.63 90 top
RA82  -  [R_0603]  34.2 34.88 180 bottom
RC1  -  [R_0402]  146.28 66.63 0 top
RC2  -  [R_0402]  122.28 68.41 90 top
RC3  -  [R_0402]  143.53 69.47 90 top
RC4  -  [R_0402]  155.6 53.96 0 bottom
RC5  -  [R_0402]  139.55 50.63 270 top
RC6  -  [R_0402]  140.44 50.63 270 top
RC7  -  [R_0402]  141.33 50.63 270 top
RC9  -  [R_0402]  157.71 49.36 0 top
RC10  -  [R_0402]  156.39 52.54 180 bottom
RC11  -  [R_0402]  156.59 51.65 180 bottom
RC12  -  [R_0402]  156.59 64.86 180 top
RC13  -  [R_0402]  156.59 66.77 180 bottom
RC14  -  [R_0402]  155.68 63.84 0 top
RC15  -  [R_0402]  155.68 62.82 0 bottom
RC16  -  [R_0402]  147.04 44.54 90 bottom
RC17  -  [R_0402]  155.68 63.71 0 bottom
RC18  -  [R_0402]  155.68 45.3 0 bottom
RC19  -  [R0402_0OHM]  155.65 57.08 0 bottom
RC20  -  [R_0402]  150.98 57.93 0 top
RC21  -  [R_0402]  148.06 44.54 90 bottom
RC22  -  [R_0402]  155.68 46.19 0 bottom
RC23  -  [R_0402]  155.68 65.74 0 top
RC25  -  [R_0402]  155.68 61.93 0 bottom
RC26  -  [R_0402]  149.76 55.58 0 top
RC27  -  [R_0402]  151.18 44.79 180 bottom
RC29  -  [R_0402]  184.71 56.35 180 bottom
RC44  -  [R_0402]  150.68 60.74 0 top
RC45  -  [R_0402]  149.58 69.29 90 top
RC46  -  [R_0402]  153.21 71.56 270 top
RC47  -  [R_0402]  45.31 35.95 90 bottom
RC48  -  [R_0402]  146.03 45.42 270 bottom
RC49  -  [R_0402]  147.8 49.87 90 top
RC50  -  [R_0402]  149.58 49.92 90 top
RC51  -  [R_0201]  150.72 67.77 270 top
RC52  -  [R_0402]  127.94 70.11 270 top
RC53  -  [R_0402]  190.6 80.26 180 bottom
RC54  -  [R_0402]  149.84 47.71 0 top
RC55  -  [R_0402]  187.2 76.78 90 bottom
RC56  -  [R_0402]  147.04 45.42 270 top
RC57  -  [R_0402]  148.82 45.42 270 top
RC58  -  [R_0402]  192.37 80.27 180 bottom
RC59  -  [R_0402]  176.2 37.4 180 top
RC60  -  [R_0402]  193.75 73.87 180 bottom
RC61  -  [R_0402]  194.12 80.27 180 bottom
RC62  -  [R_0402]  195.87 80.29 180 bottom
RC63  -  [R_0402]  62.17 51.65 270 bottom
RC64  -  [R_0402]  196.74 80.27 0 bottom
RC65  -  [R_0402]  161.01 62.87 90 top
RC66  -  [R_0402]  202.45 80.29 180 bottom
RC67  -  [R_0402]  145.69 44.48 90 top
RC69  -  [R_0402]  147.93 45.42 270 top
RC71  -  [R_0402]  109.12 77.07 0 bottom
RC72  -  [R_0402]  147.93 48.09 0 top
RC73  -  [R_0402]  152.18 44.81 0 bottom
RC74  -  [R_0402]  142.7 44.59 90 top
RC75  -  [R_0402]  143.99 42 90 top
RC77  -  [R_0402]  110.03 73.19 0 top
RC78  -  [R_0402]  110.97 77 270 bottom
RC79  -  [R_0402]  117.45 77.05 180 bottom
RC80  -  [R_0402]  115.29 77.12 270 top
RC81  -  [R_0402]  118.09 78.06 270 top
RC82  -  [R_0402]  120.88 77.68 90 top
RC83  -  [R_0402]  111.42 77.06 270 top
RC84  -  [R_0402]  112.31 76.15 90 top
RC85  -  [R_0402]  162.48 58.63 180 top
RC86  -  [R_0402]  119.86 78.57 270 top
RC87  -  [R_0402]  118.47 76.92 90 bottom
RC88  -  [R_0402]  143.1 50.63 270 top
RC89  -  [R_0402]  142.22 50.63 270 top
RC90  -  [R_0402]  113.08 67.78 180 top
RC91  -  [R_0402]  115.24 67.01 180 top
RC92  -  [R_0402]  142.72 44.54 90 bottom
RC93  -  [R_0402]  140.77 45.58 90 bottom
RC94  -  [R_0402]  139.07 47.08 0 top
RC95  -  [R_0402]  148.82 48.98 180 top
RC96  -  [R_0402]  147.47 62.44 180 top
RC97  -  [R_0603]  177.9 55.06 90 top
RC109  -  [R_0402]  107.95 72.96 270 top
RC110  -  [R_0402]  109.64 76.93 270 top
RC112  -  [R_0402]  108.75 76.93 270 top
RC113  -  [R_0402]  110.53 77.06 270 top
RC114  -  [R_0402]  117.9 69.51 270 top
RC115  -  [R_0402]  146.66 75.7 90 bottom
RC120  -  [R_0402]  112.75 76.21 90 bottom
RC121  -  [R_0402]  75.03 76.79 270 top
RC122  -  [R_0402]  78.33 75.95 90 top
RC123  -  [R_0402]  70.71 75.88 90 top
RC124  -  [R_0402]  71.6 76.79 270 top
RC126  -  [R_0402]  76.3 75.9 90 top
RC128  -  [R_0402]  64.87 76.74 270 top
RC129  -  [R_0402]  65.89 76.74 270 top
RC130  -  [R_0402]  116.82 78.06 270 top
RC131  -  [R_0402]  90.91 76.46 90 bottom
RC132  -  [R_0402]  76.43 79.33 270 top
RC133  -  [R_0402]  63.98 75.83 90 top
RC134  -  [R_0402]  89.95 76.46 90 bottom
RC135  -  [R_0402]  89 76.46 90 bottom
RC136  -  [R_0402]  79.49 73.49 180 bottom
RC137  -  [R_0402]  65.89 70.19 270 bottom
RC138  -  [R_0402]  77.19 76.82 270 top
RC139  -  [R_0402]  63.09 76.74 270 top
RC140  -  [R_0402]  135.46 72.13 270 top
RC141  -  [R_0402]  136.34 71.22 90 top
RC143  -  [R0603_0OHM]  140.36 70.82 90 top
RC152  -  [R_0402]  116.18 78.06 180 bottom
RC153  -  [R_0402]  115.42 76.21 90 bottom
RC154  -  [R0402_0OHM]  114.53 76.21 90 bottom
RC155  -  [R0402_0OHM]  114.28 76.21 90 top
RC157  -  [R_0402]  113.64 77.12 270 bottom
RC158  -  [R_0402]  113.39 78.01 270 top
RC161  -  [R_0402]  108.05 64.52 90 top
RC163  -  [R_0402]  106.99 68 180 top
RC165  -  [R_0402]  137.39 57.24 270 top
RC166  -  [R_0402]  138.9 70.53 180 top
RC167  -  [R_0402]  138.28 56.35 90 top
RC168  -  [R_0402]  139.97 69.62 270 top
RC169  -  [R0402_0OHM]  145.73 72.37 270 top
RC170  -  [R0603_0OHM]  144.76 72.22 180 top
RC171  -  [R0402_0OHM]  130.02 57.18 270 top
RC172  -  [MURAT_BLM18EG221SN1D_2P]  159.65 59.69 90 top
RC175  -  [R_0402]  150.22 75.65 90 top
RC176  -  [R_0402]  155.68 66.63 0 top
RC177  -  [R_0402]  155.68 67.52 0 top
RC178  -  [R_0402]  149.33 75.65 90 top
RC183  -  [R_0402]  151.39 52.47 180 top
RC184  -  [R_0402]  150.67 54.7 180 top
RC185  -  [R_0402]  149.33 75.7 90 bottom
RC186  -  [R_0402]  150.8 53.68 180 top
RC187  -  [R_0402]  140.54 44.74 90 top
RC188  -  [R_0402]  150.34 75.7 90 bottom
RC189  -  [R_0402]  148.44 75.7 90 bottom
RC190  -  [R_0402]  202.29 19.52 270 top
RC191  -  [R_0402]  147.55 75.7 90 bottom
RC211  -  [R0603_0OHM]  148.44 58.33 180 top
RC213  -  [R0402_0OHM]  146.15 58.25 180 top
RC214  -  [R0603_0OHM]  157.46 44.66 0 top
RC215  -  [R_0402]  144.63 44.51 90 bottom
RC216  -  [R0603_0OHM]  69.06 69.62 90 bottom
RC217  -  [R_0402]  75.54 79.33 270 top
RC218  -  [R_0402]  72.8 79.08 0 top
RC219  -  [R_0402]  74.65 78.44 90 top
RC220  -  [R_0402]  143.1 42.88 270 top
RC221  -  [R0402_0OHM]  177.14 64.4 90 bottom
RC224  -  [R_0402]  145.69 80.08 0 bottom
RC225  -  [R_0402]  145.89 78.81 180 top
RC226  -  [R_0402]  161.9 62.87 90 top
RC227  -  [R_0402]  143.99 78.79 180 top
RC228  -  [R0402_0OHM]  185.65 41.84 90 bottom
RC229  -  [R_0402]  186.54 41.84 90 bottom
RC230  -  [R_0402]  185.57 40.7 270 top
RC236  -  [R_0402]  152.38 76.62 270 bottom
RC237  -  [R_0402]  148.69 49.87 90 top
RC239  -  [R_0402]  74.02 76.79 270 top
RC240  -  [R_0402]  73 76.79 270 top
RC241  -  [R_0402]  69.7 76.79 270 top
RC242  -  [R_0402]  149.65 67.5 270 top
RC243  -  [R_0402]  145.21 47.41 270 top
RC245  -  [R_0402]  149.2 45.5 270 bottom
RC246  -  [R_0402]  156.73 48.97 180 bottom
RC247  -  [R0402_0OHM]  148.31 70.62 90 top
RC248  -  [R0402_0OHM]  155.23 67.84 0 bottom
RC272  -  [R_0402]  156.93 48.1 180 bottom
RC277  -  [R_0402]  151.49 76.62 270 bottom
RC280  -  [R_0402]  155.68 61.43 0 top
RC283  -  [R_0402]  156.57 58.12 180 bottom
RC284  -  [R_0402]  158.9 59.78 0 bottom
RC285  -  [R_0402]  158.9 60.66 0 bottom
RC288  -  [R_0402]  156.57 47.08 180 bottom
RC290  -  [R0402_0OHM]  143.92 80.08 0 bottom
RC291  -  [R_0402]  147.47 79.19 90 bottom
RC292  -  [R_0402]  156.59 59.95 180 bottom
RC293  -  [R_0402]  22.76 53.81 0 top
RC296  -  [R0402_0OHM]  150.47 46.82 0 top
RC297  -  [R0402_0OHM]  90.65 80.22 180 top
RC298  -  [R0402_0OHM]  90.65 79.33 180 top
RC299  -  [R0603_0OHM]  151.61 69.68 270 top
RC301  -  [R0402_0OHM]  156.59 65.9 180 bottom
RC304  -  [R0603_0OHM]  151.87 59.65 180 top
RC309  -  [R0603_0OHM]  147.3 76.79 270 top
RC310  -  [R0402_0OHM]  148.44 76.54 270 top
RC312  -  [R_0402]  148.76 67.5 270 top
RC313  -  [R_0402]  142.47 48.52 270 top
RC316  -  [R_0201]  152.39 70.67 180 top
RC317  -  [R_0201]  152.4 71.5 180 top
RC318  -  [MURAT_BLM18EG221SN1D_2P]  158.33 55.7 180 bottom
RC319  -  [R_0402]  143.84 45.55 270 top
RD17  -  [R_0402]  90.62 39.24 90 top
RD19  -  [R_0402]  91.5 40.13 270 top
RD21  -  [R_0402]  93.07 37.4 0 top
RD22  -  [R_0402]  155.93 38.31 180 top
RD25  -  [R_0402]  93.98 36.51 180 top
RD26  -  [R_0402]  153.9 37.42 180 top
RD35  -  [R_0402]  101.27 20.17 270 top
RD36  -  [R_0402]  134.85 20.15 270 top
RD37  -  [R_0402]  102.15 20.17 270 top
RD38  -  [R_0402]  133.96 20.15 270 top
RD45  -  [R_0402]  121.51 20.15 270 top
RD46  -  [R_0402]  122.4 20.15 270 top
RD47  -  [R_0402]  152.12 20.15 270 top
RD48  -  [R_0402]  153.01 20.15 270 top
RD51  -  [R_0402]  97.2 22.84 180 top
RD52  -  [R_0402]  116.05 20.15 270 top
RD53  -  [R_0402]  97.2 24.74 180 top
RD54  -  [R_0402]  115.16 20.15 270 top
RD55  -  [R_0402]  146.28 20.15 270 top
RD56  -  [R_0402]  145.39 20.15 270 top
RD57  -  [R_0402]  131.04 24.22 180 top
RD58  -  [R_0402]  131.04 25.49 180 top
RD59  -  [R_0402]  111.48 20.15 270 top
RD60  -  [R_0402]  141.07 20.15 270 top
RD61  -  [R_0402]  110.59 20.15 270 top
RD62  -  [R_0402]  140.18 20.15 270 top
RD63  -  [R_0402]  108.81 20.15 270 top
RD64  -  [R_0402]  138.41 20.15 270 top
RD65  -  [R_0402]  109.7 20.15 270 top
RD66  -  [R_0402]  139.29 20.15 270 top
RD67  -  [R_0402]  107.93 20.15 270 top
RD68  -  [R_0402]  137.52 20.15 270 top
RD69  -  [R_0402]  100.38 20.17 270 top
RD70  -  [R_0402]  133.07 20.15 270 top
RD71  -  [R_0402]  98.6 20.17 270 top
RD72  -  [R_0402]  131.29 20.15 270 top
RD73  -  [R_0402]  99.49 20.17 270 top
RD74  -  [R_0402]  132.18 20.15 270 top
RD75  -  [R_0402]  97.71 20.17 270 top
RD76  -  [R_0402]  130.4 20.15 270 top
RD77  -  [R_0402]  96.82 20.17 270 top
RD78  -  [R_0402]  129.52 20.15 270 top
RD79  -  [R_0402]  128.63 20.15 270 top
RD80  -  [R_0402]  159.23 20.15 270 top
RD81  -  [R_0402]  127.74 20.15 270 top
RD82  -  [R_0402]  158.34 20.15 270 top
RD83  -  [R_0402]  125.96 20.15 270 top
RD84  -  [R_0402]  156.57 20.15 270 top
RD85  -  [R_0402]  126.85 20.15 270 top
RD86  -  [R_0402]  157.46 20.15 270 top
RD87  -  [R_0402]  125.07 20.15 270 top
RD88  -  [R_0402]  155.68 20.15 270 top
RD89  -  [R_0402]  120.63 20.15 270 top
RD90  -  [R_0402]  151.23 20.15 270 top
RD91  -  [R_0402]  119.74 20.15 270 top
RD92  -  [R_0402]  149.45 20.15 270 top
RD93  -  [R_0402]  118.85 20.15 270 top
RD94  -  [R_0402]  150.34 20.15 270 top
RD95  -  [R_0402]  117.93 20.17 270 top
RD96  -  [R_0402]  148.57 20.15 270 top
RD97  -  [R_0402]  117.04 20.17 270 top
RD98  -  [R_0402]  147.68 20.15 270 top
RD99  -  [R_0402]  112.37 20.15 270 top
RD100  -  [R_0402]  144.5 20.15 270 top
RD101  -  [R_0402]  113.36 20.17 270 top
RD102  -  [R_0402]  143.61 20.15 270 top
RD103  -  [R_0402]  107.04 20.15 270 top
RD104  -  [R_0402]  135.74 20.15 270 top
RD105  -  [R_0402]  103.04 20.17 270 top
RD106  -  [R_0402]  136.63 20.15 270 top
RD107  -  [R_0402]  124.18 20.15 270 top
RD108  -  [R_0402]  153.9 20.15 270 top
RD109  -  [R_0402]  123.29 20.15 270 top
RD110  -  [R_0402]  154.79 20.15 270 top
RD111  -  [R_0402]  93.93 40.14 180 top
RD112  -  [R_0402]  93.99 39.19 180 top
RD113  -  [R_0402]  94.84 37.42 270 top
RD114  -  [R_0402]  153.01 38.31 0 top
RD115  -  [R_0402]  93.99 38.29 180 top
RD116  -  [R_0402]  155.04 39.2 0 top
RD117  -  [R_0402]  114.24 20.17 270 top
RD118  -  [R_0402]  142.72 20.15 270 top
RE2  -  [R_0402]  173.2 66.51 0 top
RE3  -  [R_0402]  173.2 62.06 0 top
RE6  -  [R_0402]  173.13 65.62 0 top
RE7  -  [R_0402]  173.2 64.73 0 top
RE13  -  [R_0402]  34.44 14.44 0 top
RE14  -  [R_0402]  37.13 14.43 180 top
RE22  -  [R_0402]  35.28 20.81 270 top
RE23  -  [R_0402]  34.39 20.81 270 top
RE24  -  [R_0402]  36.3 19.9 90 top
RE25  -  [R_0402]  184.13 74.13 270 top
RE26  -  [R_0402]  183.24 74.13 270 top
RE27  -  [R_0402]  33.38 19.9 90 top
RE31  -  [R_0402]  188.95 52.41 90 top
RE32  -  [R0402_0OHM]  188.06 55.51 90 bottom
RE33  -  [R_0402]  188.06 53.3 270 top
RE34  -  [R_0402]  191.03 51.27 0 bottom
RE35  -  [R_0402]  188.57 51.47 270 bottom
RE36  -  [R_0402]  191.95 52.16 180 bottom
RE52  -  [R_0402]  180.29 57.87 0 bottom
RE53  -  [R_0402]  182.98 57.87 180 bottom
RE54  -  [R_0402]  182.22 71.84 270 top
RE55  -  [R_0402]  174.09 59.27 180 top
RE56  -  [R_0402]  177.83 59.55 180 bottom
RE57  -  [R_0402]  185.01 55.79 270 top
RE58  -  [R_0402]  174.12 63.84 180 top
RE59  -  [R_0402]  36.35 17.95 270 top
RE60  -  [R_0402]  100.48 44.54 0 bottom
RE61  -  [R_0402]  176 57.11 270 bottom
RE62  -  [R0402_0OHM]  186.16 55.79 270 top
RE63  -  [R_0402]  184.13 55.79 270 top
RE64  -  [R_0402]  183.87 58.45 270 bottom
RE65  -  [R_0402]  172.44 60.46 90 bottom
RE66  -  [R_0402]  173.33 61.38 270 bottom
RE67  -  [R_0402]  190.65 60.28 0 top
RE68  -  [R_0402]  173.2 68.39 0 top
RE69  -  [R_0402]  177.06 70.95 0 top
RE70  -  [R_0402]  177.39 72.09 180 top
RE71  -  [R_0402]  190.65 61.17 0 top
RE72  -  [R_0402]  173.08 64.86 90 bottom
RE73  -  [R_0402]  187.17 61.3 0 bottom
RE74  -  [R_0402]  175.29 64.96 90 bottom
RE75  -  [R_0402]  173.97 64.86 90 bottom
RE76  -  [R_0402]  168.89 64.78 90 bottom
RE77  -  [R_0402]  186.92 70.95 90 top
RE78  -  [R_0402]  181.33 74.13 270 top
RE79  -  [R_0402]  190.89 64.44 90 bottom
RE80  -  [R_0402]  180.19 70.95 90 top
RE81  -  [R_0402]  189.51 58.34 270 bottom
RE82  -  [R_0402]  187.73 58.12 0 bottom
RE83  -  [R_0402]  185.65 73.36 0 top
RE84  -  [R_0402]  188.06 72.35 0 top
RE85  -  [R_0402]  171.86 61.55 270 top
RE86  -  [R_0402]  187.17 62.17 0 bottom
RE87  -  [R_0201]  177.31 61.63 90 bottom
RE88  -  [R_0201]  177.31 60.96 270 bottom
RE89  -  [R_0402]  38.41 14.87 270 top
RE90  -  [R_0402]  28.78 45.46 270 top
RE91  -  [R_0402]  195.48 48.6 0 top
RE92  -  [R_0402]  184.63 50.2 270 top
RE93  -  [R_0402]  202.07 77.01 0 bottom
RE94  -  [R_0402]  201.17 78.04 270 bottom
RE95  -  [R_0402]  201.67 56.65 90 top
RE96  -  [R_0402]  174.09 60.16 180 top
RE97  -  [R_0402]  200.71 56.65 90 top
RE98  -  [R_0402]  192.89 61.35 90 bottom
RE99  -  [R_0402]  194.79 60.21 90 bottom
RE100  -  [R_0402]  55.2 43.52 270 top
RE101  -  [R_0402]  56.16 43.52 270 top
RE102  -  [R_0402]  186.3 68.69 180 bottom
RE103  -  [R_0402]  198.08 54.5 0 top
RE104  -  [R0402_0OHM]  173.2 61.05 0 top
RE105  -  [R0402_0OHM]  177.14 63.08 0 bottom
RE107  -  [R0402_0OHM]  179.05 56.9 90 bottom
RE120  -  [R0402_0OHM]  46.25 35.95 90 bottom
RE121  -  [R_0402]  181.18 63.43 90 bottom
RH24  -  [R_0402]  158.73 50.25 180 top
RH56  -  [R_0402]  174.4 45.42 0 bottom
RH58  -  [R_0402]  174.4 44.54 0 bottom
RH59  -  [R_0402]  156.59 50.76 180 bottom
RH126  -  [R_0201]  190.89 44.03 180 top
RH127  -  [R_0402]  193.27 44.41 0 top
RH129  -  [R_0402]  153.43 52.9 0 top
RH139  -  [R_0402]  152.34 53.59 270 top
RH144  -  [R_0402]  155.55 54.31 0 top
RH145  -  [R_0402]  159.07 67.03 180 bottom
RH146  -  [R_0402]  156.52 57.87 180 top
RH147  -  [R_0402]  159.18 66.11 180 bottom
RH148  -  [R_0402]  149.78 56.6 180 top
RH149  -  [R_0402]  155.6 55.2 0 top
RH150  -  [R_0402]  155.55 53.43 0 top
RH151  -  [R_0402]  155.6 56.98 0 top
RH152  -  [R_0402]  155.6 56.09 0 top
RH153  -  [R_0402]  147.88 56.6 180 top
RH357  -  [R0603_0OHM]  69.7 78.63 90 top
RH438  -  [R_0402]  54.48 71.23 90 bottom
RH440  -  [R_0402]  158.22 64.98 0 bottom
RH441  -  [R_0402]  158.22 63.97 0 bottom
RH442  -  [SHORTPADS]  161.01 64.98 0 bottom
RH443  -  [SHORTPADS]  161.01 63.71 0 bottom
RH456  -  [R_0402]  192.13 16.04 270 top
RH461  -  [R_0402]  188.57 15.83 90 top
RH556  -  [R_0402]  155.65 59.01 0 bottom
RH557  -  [R_0402]  158.47 80.22 0 top
RH562  -  [R_0402]  48.95 22.16 270 bottom
RH563  -  [R_0402]  48.95 19.49 90 bottom
RN19  -  [R_0402]  158.65 66.38 0 top
RN20  -  [R_0402]  158.8 62.32 180 top
RP5  -  [RP_0804_8P4R]  178.1 48.71 180 bottom
RP6  -  [RP_0804_8P4R]  178.1 45.92 180 bottom
RPE5  -  [RP_0804_8P4R]  191.24 59.01 0 top
RPE7  -  [RP_0804_8P4R]  170.16 65.36 270 bottom
RT1  -  [R_0402]  50.65 68.51 180 top
RT2  -  [R_0402]  44.27 55.9 180 bottom
RT3  -  [R_0201]  37.49 52.21 90 bottom
RT4  -  [R_0201]  50.23 56.83 180 top
RT5  -  [R_0402]  49.73 66.35 0 top
RT6  -  [R_0201]  49.52 73.4 90 top
RT7  -  [R_0201]  50.09 73.41 90 top
RT8  -  [R_0201]  50.65 73.4 90 top
RT9  -  [R_0201]  51.21 73.43 90 top
RT10  -  [R_0402]  41.03 52.21 90 bottom
RT11  -  [R_0201]  36.61 68.09 0 top
RT12  -  [R_0201]  39.94 67.62 90 top
RT15  -  [R_0201]  41.25 39.39 0 top
RT16  -  [R_0201]  51.32 39.2 180 top
RT17  -  [R_0201]  51.32 40.34 180 top
RT18  -  [R_0201]  51.32 38.31 180 top
RT21  -  [R_0201]  50.23 57.46 180 top
RT22  -  [R_0201]  45.95 53.04 90 bottom
RT23  -  [R_0201]  46.53 53.04 90 bottom
RT25  -  [R_0201]  38.09 52.24 90 bottom
RT26  -  [R_0201]  39.27 52.24 90 bottom
RT33  -  [R_0201]  52.15 55.32 270 top
RT34  -  [R_0201]  52.73 55.32 270 top
RT35  -  [R_0201]  44.69 53.04 90 bottom
RT36  -  [R_0201]  44.12 53.04 90 bottom
RT37  -  [R_0201]  45.26 52.78 90 bottom
RT38  -  [R_0201]  36.35 52.26 90 bottom
RT39  -  [R_0201]  38.68 52.24 90 bottom
RT40  -  [R_0201]  34.23 56.64 0 top
RT43  -  [R_0201]  42.66 55.71 90 bottom
RT44  -  [R_0201]  34.7 57.84 0 top
RT45  -  [R_0201]  34.7 57.21 0 top
RT46  -  [R_0402]  33.43 58.1 180 top
RT47  -  [R_0201]  40.3 52.66 90 bottom
RT48  -  [R_0201]  32.87 59.32 0 top
RT49  -  [R_0201]  41.31 54.53 270 bottom
RT50  -  [R_0201]  35.62 55.43 90 bottom
RT51  -  [R_0201]  28.37 47.41 0 top
RT52  -  [R_0201]  35.4 56.04 90 top
RT113  -  [R_0402]  33.43 57.21 180 top
RT114  -  [R_0603]  46.84 47.2 180 top
RT119  -  [R_0201]  36.92 52.26 90 bottom
RT120  -  [R_0201]  28.97 46.2 90 top
RT121  -  [R_0201]  29.62 46.18 90 top
RT164  -  [R_0201]  39.35 68.21 270 top
RT187  -  [R_0201]  18.81 63.76 180 top
RT188  -  [R_0201]  18.81 64.32 180 top
RT190  -  [R_0402]  23.65 66.25 90 top
RT199  -  [R_0402]  22.47 57.62 180 bottom
RT200  -  [R_0402]  22.2 56.14 180 bottom
RT201  -  [R_0402]  18.78 68.7 270 top
RT241  -  [R_0603]  24.68 46.47 90 bottom
RT242  -  [R_0402]  179.82 53.9 180 top
RT243  -  [R_0201]  36.61 67.51 0 top
RTCR1  -  [R_0402]  13.74 8.85 0 top
RTCR2  -  [R_0402]  15.02 12.73 90 top
RZ75  -  [R_0402]  167.54 67.78 0 top
RZ76  -  [R0402_0OHM]  166.85 48.85 180 top
SW1  -  [SW_SSAL120100_3P]  166.09 48.66 180 bottom
SW2  -  [SW_SKRBAAE010_4P]  191.75 76.11 90 top
